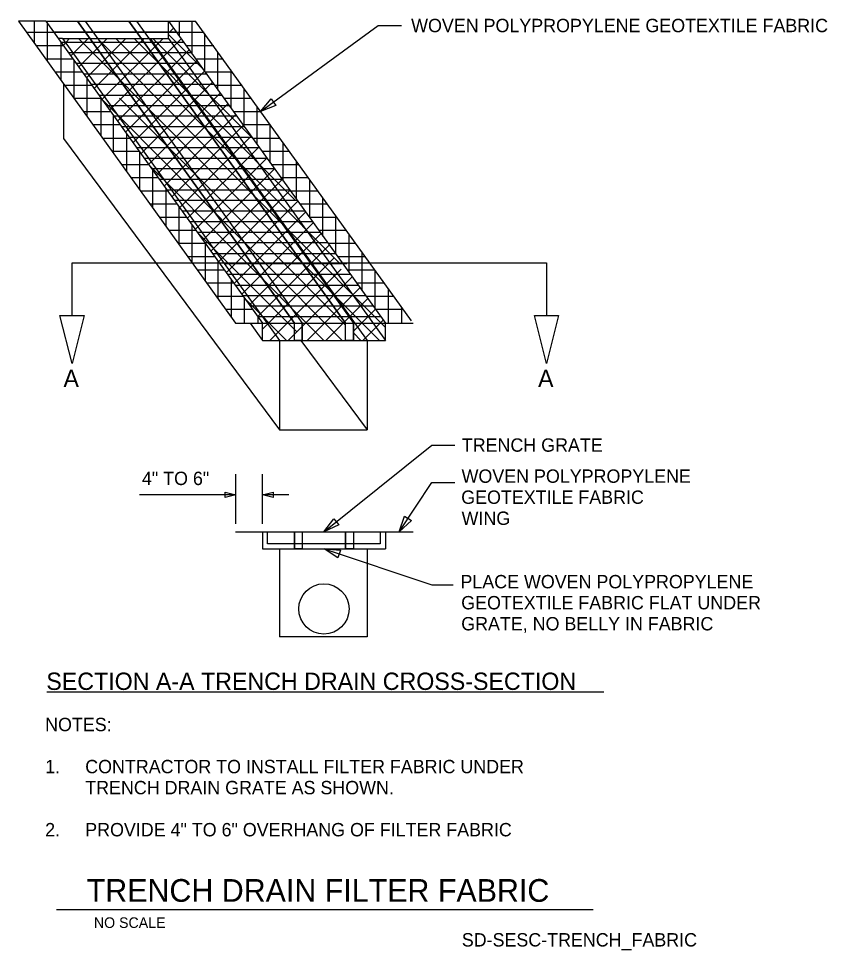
# Model space of a CAD drawing. Extents: x 10031.7 to 10094.9, y 10133.2 to 10206.1.
import ezdxf

# ---------------------------------------------------------------- set-up
doc = ezdxf.new("R2010")
doc.units = 0
for name, color, linetype in [('Default', 7, 'Continuous'), ('G-ANNO-NPLT', 7, 'Continuous'), ('G-ANNO-TEXT', 7, 'Continuous'), ('G-ANNO-TTXT', 7, 'Continuous'), ('G-DETL-LINE', 7, 'Continuous'), ('G-DETL-OTLN', 7, 'Continuous')]:
    doc.layers.add(name, color=color, linetype=linetype)

# ---------------------------------------------------------------- blocks, each defined once
blk = doc.blocks.new('TERARR')
at = {"layer": 'Default'}
blk.add_lwpolyline([(-0.667, 0.167), (0, 0), (-0.667, -0.167)], close=True, dxfattribs=at)

msp = doc.modelspace()

# ---------------------------------------------------------------- linework, layer by layer
at = {"layer": 'G-ANNO-NPLT'}
for p, q in [((10043.408, 10204.927), (10043.792, 10205.31)), ((10035.171, 10203.946), (10035.659, 10204.506)), ((10035.758, 10203.129), (10037.138, 10204.506)), ((10059.885, 10180.905), (10036.362, 10204.506)), ((10036.374, 10202.272), (10038.613, 10204.506)), ((10036.986, 10201.419), (10040.08, 10204.506)), ((10037.584, 10200.587), (10041.511, 10204.506)), ((10060.362, 10181.922), (10037.853, 10204.506)), ((10038.199, 10199.73), (10042.986, 10204.506)), ((10038.796, 10198.9), (10044.388, 10204.48)), ((10056.804, 10186.921), (10039.277, 10204.506)), ((10053.31, 10191.863), (10040.709, 10204.506)), ((10049.839, 10196.832), (10042.19, 10204.506)), ((10046.032, 10202.192), (10043.408, 10204.824)), ((10039.421, 10198.03), (10045.013, 10203.609)), ((10040.035, 10197.175), (10045.627, 10202.755)), ((10040.623, 10196.357), (10046.215, 10201.936)), ((10041.24, 10195.497), (10046.832, 10201.077)), ((10056.99, 10180.905), (10038.128, 10199.829)), ((10057.246, 10182.105), (10039.581, 10199.829)), ((10041.852, 10194.645), (10047.445, 10200.224)), ((10042.449, 10193.815), (10048.041, 10199.395)), ((10043.061, 10192.962), (10048.654, 10198.542)), ((10043.656, 10192.134), (10049.249, 10197.713)), ((10044.272, 10191.277), (10049.864, 10196.856)), ((10044.872, 10190.442), (10050.464, 10196.021)), ((10055.55, 10180.905), (10041.845, 10194.655)), ((10045.491, 10189.58), (10051.083, 10195.159)), ((10046.098, 10188.734), (10051.691, 10194.314)), ((10046.703, 10187.892), (10052.296, 10193.472)), ((10047.307, 10187.051), (10052.9, 10192.631)), ((10047.919, 10186.2), (10053.511, 10191.78)), ((10048.531, 10185.348), (10054.123, 10190.928)), ((10049.125, 10184.521), (10054.718, 10190.1)), ((10053.422, 10181.566), (10045.636, 10189.378)), ((10049.733, 10183.675), (10055.325, 10189.255)), ((10050.378, 10182.777), (10055.97, 10188.357)), ((10050.762, 10181.788), (10056.354, 10187.368)), ((10051.318, 10180.905), (10056.911, 10186.484)), ((10052.759, 10180.905), (10057.747, 10185.882)), ((10054.247, 10180.905), (10058.369, 10185.017)), ((10052.618, 10180.905), (10049.413, 10184.12)), ((10055.705, 10180.905), (10058.978, 10184.17)), ((10057.856, 10181.617), (10059.578, 10183.335)), ((10058.594, 10180.905), (10060.184, 10182.49)), ((10058.443, 10180.905), (10057.856, 10181.494))]:
    msp.add_line(p, q, dxfattribs=at)
at = {"layer": 'G-ANNO-TEXT'}
for p, q in [((10048.667, 10166.568), (10048.667, 10170.441)), ((10048.667, 10166.568), (10048.667, 10170.441)), ((10050.751, 10166.568), (10050.751, 10170.441)), ((10050.751, 10166.568), (10050.751, 10170.441)), ((10048.667, 10168.843), (10041.126, 10168.843)), ((10048.667, 10168.843), (10044.418, 10168.843)), ((10052.808, 10168.843), (10050.751, 10168.843)), ((10052.808, 10168.843), (10050.751, 10168.843)), ((10034.647, 10136.422), (10076.6, 10136.422))]:
    msp.add_line(p, q, dxfattribs=at)
for points in [[(10050.591, 10198.801), (10059.802, 10205.516), (10061.602, 10205.516)], [(10050.592, 10198.802), (10059.802, 10205.516), (10061.602, 10205.516)], [(10035.863, 10182.851), (10035.863, 10186.974), (10072.952, 10186.974), (10072.952, 10182.851)], [(10035.863, 10182.851), (10035.863, 10186.974), (10072.952, 10186.974), (10072.952, 10182.851)], [(10055.541, 10165.946), (10063.993, 10172.728), (10065.779, 10172.728)], [(10061.44, 10165.946), (10063.993, 10169.798), (10065.779, 10169.798)], [(10061.44, 10165.946), (10063.993, 10169.798), (10065.779, 10169.798)], [(10055.562, 10164.608), (10063.979, 10161.816), (10065.657, 10161.816)], [(10055.562, 10164.608), (10063.979, 10161.816), (10065.657, 10161.816)]]:
    msp.add_lwpolyline(points, dxfattribs=at)
at = {"layer": 'G-ANNO-TTXT'}
msp.add_line((10033.884, 10153.437), (10077.44, 10153.437), dxfattribs=at)
at = {"layer": 'G-DETL-LINE'}
for p, q in [((10032.907, 10205.844), (10032.907, 10204.152)), ((10032.907, 10205.844), (10032.907, 10204.152)), ((10033.808, 10205.844), (10050.762, 10182.243)), ((10033.808, 10205.844), (10040.624, 10205.844)), ((10033.808, 10205.844), (10050.762, 10182.243)), ((10033.808, 10205.844), (10040.624, 10205.844)), ((10033.928, 10205.677), (10033.928, 10202.731)), ((10033.928, 10205.677), (10033.928, 10202.731)), ((10043.408, 10205.844), (10060.362, 10182.243)), ((10043.408, 10205.844), (10060.362, 10182.243)), ((10044.226, 10205.844), (10044.226, 10204.706)), ((10044.226, 10205.844), (10044.226, 10204.706)), ((10045.231, 10205.844), (10045.231, 10203.306)), ((10045.231, 10205.844), (10045.231, 10203.306)), ((10032.309, 10204.985), (10046.196, 10204.985)), ((10032.309, 10204.985), (10046.196, 10204.985)), ((10034.401, 10205.017), (10044.002, 10205.017)), ((10034.401, 10205.017), (10044.002, 10205.017)), ((10046.247, 10201.892), (10046.247, 10204.888)), ((10046.247, 10201.892), (10046.247, 10204.888)), ((10035.117, 10204.506), (10034.769, 10204.506)), ((10035.117, 10204.506), (10034.769, 10204.506)), ((10034.98, 10204.212), (10044.581, 10204.212)), ((10034.98, 10204.212), (10034.98, 10201.266)), ((10034.98, 10204.212), (10044.581, 10204.212)), ((10034.98, 10204.212), (10034.98, 10201.266)), ((10035.117, 10204.506), (10052.071, 10180.905)), ((10035.117, 10204.506), (10052.071, 10180.905)), ((10041.97, 10204.506), (10058.924, 10180.905)), ((10041.97, 10204.506), (10058.924, 10180.905)), ((10043.408, 10204.506), (10060.362, 10180.905)), ((10043.408, 10204.506), (10060.362, 10180.905)), ((10033.055, 10203.946), (10035.171, 10203.946)), ((10033.055, 10203.946), (10035.171, 10203.946)), ((10035.563, 10203.4), (10045.164, 10203.4)), ((10035.563, 10203.4), (10045.164, 10203.4)), ((10044.772, 10203.946), (10046.943, 10203.946)), ((10044.772, 10203.946), (10046.943, 10203.946)), ((10047.265, 10200.474), (10047.265, 10203.47)), ((10047.265, 10200.474), (10047.265, 10203.47)), ((10033.793, 10202.918), (10035.909, 10202.918)), ((10033.793, 10202.918), (10035.909, 10202.918)), ((10035.998, 10202.794), (10035.998, 10199.848)), ((10035.998, 10202.794), (10035.998, 10199.848)), ((10045.51, 10202.918), (10047.681, 10202.918)), ((10045.51, 10202.918), (10047.681, 10202.918)), ((10036.158, 10202.572), (10045.758, 10202.572)), ((10036.158, 10202.572), (10045.758, 10202.572)), ((10048.291, 10199.046), (10048.291, 10202.043)), ((10048.291, 10199.046), (10048.291, 10202.043)), ((10034.531, 10201.892), (10036.647, 10201.892)), ((10034.531, 10201.892), (10036.647, 10201.892)), ((10036.759, 10201.735), (10046.36, 10201.735)), ((10036.759, 10201.735), (10046.36, 10201.735)), ((10037.029, 10201.36), (10037.029, 10198.414)), ((10037.029, 10201.36), (10037.029, 10198.414)), ((10046.247, 10201.892), (10048.418, 10201.892)), ((10046.247, 10201.892), (10048.418, 10201.892)), ((10035.197, 10200.987), (10035.197, 10196.694)), ((10035.197, 10200.987), (10035.197, 10196.694)), ((10035.277, 10200.853), (10037.393, 10200.853)), ((10035.277, 10200.853), (10037.393, 10200.853)), ((10037.343, 10200.922), (10046.944, 10200.922)), ((10037.343, 10200.922), (10046.944, 10200.922)), ((10046.993, 10200.853), (10049.164, 10200.853)), ((10046.993, 10200.853), (10049.164, 10200.853)), ((10049.32, 10197.614), (10049.32, 10200.611)), ((10049.32, 10197.614), (10049.32, 10200.611)), ((10036.008, 10199.835), (10038.124, 10199.835)), ((10036.008, 10199.835), (10038.124, 10199.835)), ((10037.951, 10200.077), (10047.551, 10200.077)), ((10037.951, 10200.077), (10047.551, 10200.077)), ((10038.124, 10199.835), (10038.124, 10196.89)), ((10038.124, 10199.835), (10038.124, 10196.89)), ((10047.724, 10199.835), (10049.896, 10199.835)), ((10047.724, 10199.835), (10049.896, 10199.835)), ((10038.536, 10199.262), (10048.136, 10199.262)), ((10038.536, 10199.262), (10048.136, 10199.262)), ((10050.332, 10196.205), (10050.332, 10199.202)), ((10050.332, 10196.205), (10050.332, 10199.202)), ((10036.759, 10198.79), (10038.875, 10198.79)), ((10036.759, 10198.79), (10038.875, 10198.79)), ((10039.08, 10198.504), (10039.08, 10195.558)), ((10039.08, 10198.504), (10039.08, 10195.558)), ((10039.117, 10198.452), (10048.718, 10198.452)), ((10039.117, 10198.452), (10048.718, 10198.452)), ((10048.475, 10198.79), (10050.646, 10198.79)), ((10048.475, 10198.79), (10050.646, 10198.79)), ((10037.492, 10197.77), (10039.608, 10197.77)), ((10037.492, 10197.77), (10039.608, 10197.77)), ((10039.719, 10197.614), (10049.32, 10197.614)), ((10039.719, 10197.614), (10049.32, 10197.614)), ((10049.208, 10197.77), (10051.379, 10197.77)), ((10049.208, 10197.77), (10051.379, 10197.77)), ((10051.349, 10194.79), (10051.349, 10197.786)), ((10051.349, 10194.79), (10051.349, 10197.786)), ((10040.122, 10197.054), (10040.122, 10194.108)), ((10040.122, 10197.054), (10040.122, 10194.108)), ((10035.197, 10196.694), (10052.071, 10173.92)), ((10035.197, 10196.694), (10052.071, 10173.92)), ((10038.243, 10196.724), (10040.359, 10196.724)), ((10038.243, 10196.724), (10040.359, 10196.724)), ((10040.305, 10196.799), (10049.905, 10196.799)), ((10040.305, 10196.799), (10049.905, 10196.799)), ((10049.959, 10196.724), (10052.13, 10196.724)), ((10049.959, 10196.724), (10052.13, 10196.724)), ((10052.374, 10193.362), (10052.374, 10196.359)), ((10052.374, 10193.362), (10052.374, 10196.359)), ((10038.976, 10195.703), (10041.092, 10195.703)), ((10038.976, 10195.703), (10041.092, 10195.703)), ((10040.887, 10195.989), (10050.487, 10195.989)), ((10040.887, 10195.989), (10050.487, 10195.989)), ((10041.143, 10195.633), (10041.143, 10192.688)), ((10041.143, 10195.633), (10041.143, 10192.688)), ((10050.693, 10195.703), (10052.864, 10195.703)), ((10050.693, 10195.703), (10052.864, 10195.703)), ((10039.721, 10194.667), (10041.837, 10194.667)), ((10039.721, 10194.667), (10041.837, 10194.667)), ((10041.489, 10195.151), (10051.089, 10195.151)), ((10041.489, 10195.151), (10051.089, 10195.151)), ((10051.437, 10194.667), (10053.608, 10194.667)), ((10051.437, 10194.667), (10053.608, 10194.667)), ((10053.401, 10191.933), (10053.401, 10194.929)), ((10053.401, 10191.933), (10053.401, 10194.929)), ((10042.074, 10194.336), (10051.675, 10194.336)), ((10042.074, 10194.336), (10051.675, 10194.336)), ((10042.154, 10194.226), (10042.154, 10191.28)), ((10042.154, 10194.226), (10042.154, 10191.28)), ((10040.46, 10193.638), (10042.576, 10193.638)), ((10040.46, 10193.638), (10042.576, 10193.638)), ((10042.663, 10193.516), (10052.264, 10193.516)), ((10042.663, 10193.516), (10052.264, 10193.516)), ((10052.176, 10193.638), (10054.347, 10193.638)), ((10052.176, 10193.638), (10054.347, 10193.638)), ((10054.449, 10190.474), (10054.449, 10193.47)), ((10054.449, 10190.474), (10054.449, 10193.47)), ((10041.21, 10192.594), (10043.326, 10192.594)), ((10041.21, 10192.594), (10043.326, 10192.594)), ((10043.184, 10192.791), (10043.184, 10189.845)), ((10043.184, 10192.791), (10043.184, 10189.845)), ((10043.265, 10192.678), (10052.866, 10192.678)), ((10043.265, 10192.678), (10052.866, 10192.678)), ((10052.926, 10192.594), (10055.097, 10192.594)), ((10052.926, 10192.594), (10055.097, 10192.594)), ((10043.851, 10191.863), (10053.451, 10191.863)), ((10043.851, 10191.863), (10053.451, 10191.863)), ((10055.463, 10189.063), (10055.463, 10192.059)), ((10055.463, 10189.063), (10055.463, 10192.059)), ((10041.938, 10191.58), (10044.054, 10191.58)), ((10041.938, 10191.58), (10044.054, 10191.58)), ((10044.206, 10191.369), (10044.206, 10188.423)), ((10044.206, 10191.369), (10044.206, 10188.423)), ((10044.448, 10191.031), (10054.049, 10191.031)), ((10044.448, 10191.031), (10054.049, 10191.031)), ((10053.655, 10191.58), (10055.826, 10191.58)), ((10053.655, 10191.58), (10055.826, 10191.58)), ((10042.691, 10190.532), (10044.807, 10190.532)), ((10042.691, 10190.532), (10044.807, 10190.532)), ((10054.407, 10190.532), (10056.578, 10190.532)), ((10054.407, 10190.532), (10056.578, 10190.532)), ((10056.488, 10187.635), (10056.488, 10190.632)), ((10056.488, 10187.635), (10056.488, 10190.632)), ((10045.051, 10190.193), (10054.651, 10190.193)), ((10045.051, 10190.193), (10054.651, 10190.193)), ((10045.229, 10189.944), (10045.229, 10186.999)), ((10045.229, 10189.944), (10045.229, 10186.999)), ((10043.416, 10189.523), (10045.532, 10189.523)), ((10043.416, 10189.523), (10045.532, 10189.523)), ((10045.636, 10189.378), (10055.236, 10189.378)), ((10045.636, 10189.378), (10055.236, 10189.378)), ((10055.132, 10189.523), (10057.303, 10189.523)), ((10055.132, 10189.523), (10057.303, 10189.523)), ((10057.518, 10186.202), (10057.518, 10189.199)), ((10057.518, 10186.202), (10057.518, 10189.199)), ((10044.154, 10188.496), (10046.27, 10188.496)), ((10044.154, 10188.496), (10046.27, 10188.496)), ((10046.234, 10188.546), (10055.834, 10188.546)), ((10046.234, 10188.546), (10055.834, 10188.546)), ((10046.27, 10188.496), (10046.27, 10185.55)), ((10046.27, 10188.496), (10046.27, 10185.55)), ((10055.87, 10188.496), (10058.041, 10188.496)), ((10055.87, 10188.496), (10058.041, 10188.496)), ((10044.904, 10187.451), (10047.02, 10187.451)), ((10044.904, 10187.451), (10047.02, 10187.451)), ((10046.851, 10187.686), (10056.452, 10187.686)), ((10046.851, 10187.686), (10056.452, 10187.686)), ((10056.621, 10187.451), (10058.792, 10187.451)), ((10056.621, 10187.451), (10058.792, 10187.451)), ((10058.542, 10184.776), (10058.542, 10187.773)), ((10058.542, 10184.776), (10058.542, 10187.773)), ((10047.253, 10187.127), (10047.253, 10184.182)), ((10047.253, 10187.127), (10047.253, 10184.182)), ((10047.749, 10186.921), (10057.349, 10186.921)), ((10047.749, 10186.921), (10057.349, 10186.921)), ((10045.644, 10186.421), (10047.76, 10186.421)), ((10045.644, 10186.421), (10047.76, 10186.421)), ((10048.003, 10186.083), (10057.603, 10186.083)), ((10048.003, 10186.083), (10057.603, 10186.083)), ((10057.36, 10186.421), (10059.532, 10186.421)), ((10057.36, 10186.421), (10059.532, 10186.421)), ((10059.567, 10183.349), (10059.567, 10186.346)), ((10059.567, 10183.349), (10059.567, 10186.346)), ((10046.372, 10185.408), (10048.488, 10185.408)), ((10046.372, 10185.408), (10048.488, 10185.408)), ((10048.294, 10185.678), (10048.294, 10182.732)), ((10048.294, 10185.678), (10048.294, 10182.732)), ((10048.621, 10185.223), (10058.221, 10185.223)), ((10048.621, 10185.223), (10058.221, 10185.223)), ((10058.088, 10185.408), (10060.259, 10185.408)), ((10058.088, 10185.408), (10060.259, 10185.408)), ((10060.604, 10182.243), (10060.604, 10184.925)), ((10060.604, 10182.243), (10060.604, 10184.925)), ((10047.117, 10184.37), (10049.233, 10184.37)), ((10047.117, 10184.37), (10049.233, 10184.37)), ((10049.201, 10184.415), (10058.801, 10184.415)), ((10049.201, 10184.415), (10058.801, 10184.415)), ((10049.316, 10184.255), (10049.316, 10182.243)), ((10049.316, 10184.255), (10049.316, 10182.243)), ((10058.833, 10184.37), (10061.005, 10184.37)), ((10058.833, 10184.37), (10061.005, 10184.37)), ((10047.851, 10183.349), (10049.967, 10183.349)), ((10047.851, 10183.349), (10049.967, 10183.349)), ((10049.787, 10183.599), (10059.388, 10183.599)), ((10049.787, 10183.599), (10059.388, 10183.599)), ((10059.567, 10183.349), (10061.738, 10183.349)), ((10059.567, 10183.349), (10061.738, 10183.349)), ((10061.651, 10182.243), (10061.651, 10183.475)), ((10061.651, 10182.243), (10061.651, 10183.475)), ((10050.378, 10182.777), (10059.978, 10182.777)), ((10050.378, 10182.777), (10050.378, 10182.243)), ((10050.378, 10182.777), (10059.978, 10182.777)), ((10050.378, 10182.777), (10050.378, 10182.243)), ((10049.8, 10182.243), (10050.762, 10180.905)), ((10049.8, 10182.243), (10050.762, 10180.905)), ((10050.762, 10182.243), (10060.362, 10182.243)), ((10050.762, 10182.243), (10060.362, 10182.243)), ((10052.071, 10180.905), (10052.071, 10173.92)), ((10052.071, 10180.905), (10052.071, 10173.92)), ((10053.749, 10180.905), (10058.924, 10173.92)), ((10053.749, 10180.905), (10058.924, 10173.92)), ((10058.924, 10180.905), (10058.924, 10173.92)), ((10058.924, 10180.905), (10058.924, 10173.92)), ((10052.071, 10173.92), (10058.924, 10173.92)), ((10052.071, 10173.92), (10058.924, 10173.92)), ((10050.762, 10165.946), (10060.362, 10165.946)), ((10050.762, 10165.946), (10060.362, 10165.946)), ((10052.071, 10164.608), (10052.071, 10157.742)), ((10052.071, 10164.608), (10052.071, 10157.742)), ((10058.924, 10164.608), (10058.924, 10157.742)), ((10058.924, 10164.608), (10058.924, 10157.742)), ((10058.924, 10157.742), (10052.071, 10157.742)), ((10058.924, 10157.742), (10052.071, 10157.742))]:
    msp.add_line(p, q, dxfattribs=at)
msp.add_circle((10055.549, 10159.92), 1.964, dxfattribs=at)
msp.add_circle((10055.549, 10159.92), 1.964, dxfattribs=at)
at = {"layer": 'G-DETL-OTLN'}
for p, q in [((10033.808, 10205.844), (10031.692, 10205.844)), ((10031.692, 10205.844), (10048.646, 10182.243)), ((10033.808, 10205.844), (10031.692, 10205.844)), ((10031.692, 10205.844), (10048.646, 10182.243)), ((10036.293, 10205.844), (10053.247, 10182.243)), ((10036.293, 10205.844), (10036.903, 10205.844)), ((10036.293, 10205.844), (10053.247, 10182.243)), ((10036.293, 10205.844), (10036.903, 10205.844)), ((10036.903, 10205.844), (10053.857, 10182.243)), ((10036.903, 10205.844), (10053.857, 10182.243)), ((10040.292, 10205.844), (10057.246, 10182.243)), ((10040.292, 10205.844), (10040.902, 10205.844)), ((10040.292, 10205.844), (10057.246, 10182.243)), ((10040.292, 10205.844), (10040.902, 10205.844)), ((10040.624, 10205.844), (10045.511, 10205.844)), ((10040.624, 10205.844), (10045.511, 10205.844)), ((10040.902, 10205.844), (10057.856, 10182.243)), ((10040.902, 10205.844), (10057.856, 10182.243)), ((10043.408, 10204.506), (10043.408, 10205.844)), ((10043.408, 10204.506), (10043.408, 10205.844)), ((10062.389, 10182.447), (10045.511, 10205.844)), ((10062.389, 10182.447), (10045.511, 10205.844)), ((10035.117, 10204.506), (10043.408, 10204.506)), ((10035.117, 10204.506), (10043.408, 10204.506)), ((10048.646, 10182.243), (10050.762, 10182.243)), ((10048.646, 10182.243), (10050.762, 10182.243)), ((10050.762, 10180.905), (10050.762, 10182.243)), ((10050.762, 10180.905), (10050.762, 10182.243)), ((10053.247, 10180.905), (10053.247, 10182.243)), ((10053.247, 10180.905), (10053.247, 10182.243)), ((10053.857, 10180.905), (10053.857, 10182.243)), ((10053.857, 10180.905), (10053.857, 10182.243)), ((10057.246, 10180.905), (10057.246, 10182.243)), ((10057.246, 10180.905), (10057.246, 10182.243)), ((10057.856, 10180.905), (10057.856, 10182.243)), ((10057.856, 10180.905), (10057.856, 10182.243)), ((10060.362, 10180.905), (10060.362, 10182.243)), ((10060.362, 10182.243), (10062.536, 10182.243)), ((10060.362, 10180.905), (10060.362, 10182.243)), ((10060.362, 10182.243), (10062.536, 10182.243)), ((10050.762, 10180.905), (10060.362, 10180.905)), ((10050.762, 10180.905), (10060.362, 10180.905)), ((10048.646, 10165.946), (10050.762, 10165.946)), ((10048.646, 10165.946), (10050.762, 10165.946)), ((10050.762, 10165.946), (10050.762, 10164.608)), ((10050.762, 10165.946), (10050.762, 10164.608)), ((10053.247, 10165.946), (10053.247, 10164.608)), ((10053.247, 10165.946), (10053.247, 10164.608)), ((10053.857, 10165.946), (10053.857, 10164.608)), ((10053.857, 10165.946), (10053.857, 10164.608)), ((10057.246, 10165.946), (10057.246, 10164.608)), ((10057.246, 10165.946), (10057.246, 10164.608)), ((10057.856, 10165.946), (10057.856, 10164.608)), ((10057.856, 10165.946), (10057.856, 10164.608)), ((10060.362, 10165.946), (10060.362, 10164.608)), ((10060.362, 10165.946), (10062.519, 10165.946)), ((10060.362, 10165.946), (10060.362, 10164.608)), ((10060.362, 10165.946), (10062.519, 10165.946)), ((10050.762, 10164.608), (10060.362, 10164.608)), ((10050.762, 10164.608), (10060.362, 10164.608))]:
    msp.add_line(p, q, dxfattribs=at)
for points in [[(10053.247, 10180.905), (10053.247, 10182.243), (10036.293, 10205.844), (10036.903, 10205.844), (10053.857, 10182.243), (10053.857, 10180.905)], [(10053.247, 10180.905), (10053.247, 10182.243), (10036.293, 10205.844), (10036.903, 10205.844), (10053.857, 10182.243), (10053.857, 10180.905)], [(10057.246, 10180.905), (10057.246, 10182.243), (10040.292, 10205.844), (10040.902, 10205.844), (10057.856, 10182.243), (10057.856, 10180.905)], [(10057.246, 10180.905), (10057.246, 10182.243), (10040.292, 10205.844), (10040.902, 10205.844), (10057.856, 10182.243), (10057.856, 10180.905)], [(10051.13, 10165.946), (10059.951, 10165.946), (10059.951, 10165.004), (10051.13, 10165.004)], [(10053.247, 10165.946), (10053.857, 10165.946), (10053.857, 10164.608), (10053.247, 10164.608)], [(10053.247, 10165.946), (10053.857, 10165.946), (10053.857, 10164.608), (10053.247, 10164.608)], [(10057.246, 10165.946), (10057.856, 10165.946), (10057.856, 10164.608), (10057.246, 10164.608)], [(10057.246, 10165.946), (10057.856, 10165.946), (10057.856, 10164.608), (10057.246, 10164.608)]]:
    msp.add_lwpolyline(points, close=True, dxfattribs=at)

# ---------------------------------------------------------------- block references
at = {"layer": 'G-ANNO-TEXT'}
for p, xscale, yscale, rotation in [((10050.591, 10198.801), 1.8750000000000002, 1.8750000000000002, -144.26046848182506), ((10035.863, 10179.101), 5.625, 5.624999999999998, -90.00000000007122), ((10035.863, 10179.101), 5.625, 5.624999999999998, -90.00000000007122), ((10072.952, 10179.101), 5.625, 5.624999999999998, -90.00000000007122), ((10072.952, 10179.101), 5.625, 5.624999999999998, -90.00000000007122), ((10050.751, 10168.843), 1.25, 1.25, 180), ((10050.751, 10168.843), 1.25, 1.25, 180), ((10061.44, 10165.946), 1.8750000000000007, 1.8750000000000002, -123.03272012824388), ((10061.44, 10165.946), 1.8750000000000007, 1.8750000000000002, -123.03272012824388), ((10055.541, 10165.946), 1.8750000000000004, 1.8750000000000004, -141.4519840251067), ((10055.562, 10164.608), 1.8750000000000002, 1.875, 161.65311671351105), ((10055.562, 10164.608), 1.8750000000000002, 1.875, 161.65311671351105)]:
    msp.add_blockref('TERARR', p, dxfattribs=dict(at, xscale=xscale, yscale=yscale, rotation=rotation))
at = {"layer": 'G-ANNO-TEXT', "xscale": 1.25, "yscale": 1.25}
msp.add_blockref('TERARR', (10048.667, 10168.843), dxfattribs=at)
msp.add_blockref('TERARR', (10048.667, 10168.843), dxfattribs=at)

# ---------------------------------------------------------------- texts
at = {"layer": 'G-ANNO-TEXT'}
for s, height, p in [('WOVEN POLYPROPYLENE GEOTEXTILE FABRIC', 1.044, (10062.369, 10204.995)), ('WOVEN POLYPROPYLENE GEOTEXTILE FABRIC', 1.044, (10062.369, 10204.995)), ('TRENCH GRATE', 1.044, (10066.328, 10172.205)), ('4" TO 6"', 1.044, (10041.329, 10169.602)), ('WOVEN POLYPROPYLENE', 1.044, (10066.31, 10169.776)), ('WOVEN POLYPROPYLENE', 1.044, (10066.31, 10169.776)), ('GEOTEXTILE FABRIC', 1.044, (10066.282, 10168.132)), ('GEOTEXTILE FABRIC', 1.044, (10066.282, 10168.132)), ('WING', 1.044, (10066.31, 10166.488)), ('WING', 1.044, (10066.31, 10166.488)), ('PLACE WOVEN POLYPROPYLENE', 1.044, (10066.222, 10161.53)), ('PLACE WOVEN POLYPROPYLENE', 1.044, (10066.222, 10161.53)), ('GEOTEXTILE FABRIC FLAT UNDER ', 1.044, (10066.282, 10159.886)), ('GEOTEXTILE FABRIC FLAT UNDER ', 1.044, (10066.282, 10159.886)), ('GRATE, NO BELLY IN FABRIC', 1.044, (10066.282, 10158.242)), ('GRATE, NO BELLY IN FABRIC', 1.044, (10066.282, 10158.242)), ('NOTES:', 1.044, (10033.764, 10150.366)), ('1.', 1.044, (10033.764, 10147.078)), ('CONTRACTOR TO INSTALL FILTER FABRIC UNDER', 1.044, (10036.896, 10147.078)), ('TRENCH DRAIN GRATE AS SHOWN.', 1.044, (10036.896, 10145.434)), ('2.', 1.044, (10033.764, 10142.146)), ('PROVIDE 4" TO 6" OVERHANG OF FILTER FABRIC', 1.044, (10036.896, 10142.146)), ('NO SCALE', 0.828, (10037.572, 10134.988)), ('NO SCALE', 0.828, (10037.572, 10134.988)), ('SD-SESC-TRENCH_FABRIC', 1.044, (10066.328, 10133.537))]:
    msp.add_text(s, height=height, dxfattribs=at).set_placement(p)
at = {"layer": 'G-ANNO-TTXT'}
for s, height, p in [('A', 1.356, (10035.196, 10177.258)), ('A', 1.356, (10072.287, 10177.258)), ('SECTION A-A TRENCH DRAIN CROSS-SECTION', 1.356, (10033.856, 10153.589)), ('TRENCH DRAIN FILTER FABRIC', 1.776, (10037.012, 10137.03))]:
    msp.add_text(s, height=height, dxfattribs=at).set_placement(p)

doc.saveas('drawing.dxf')
